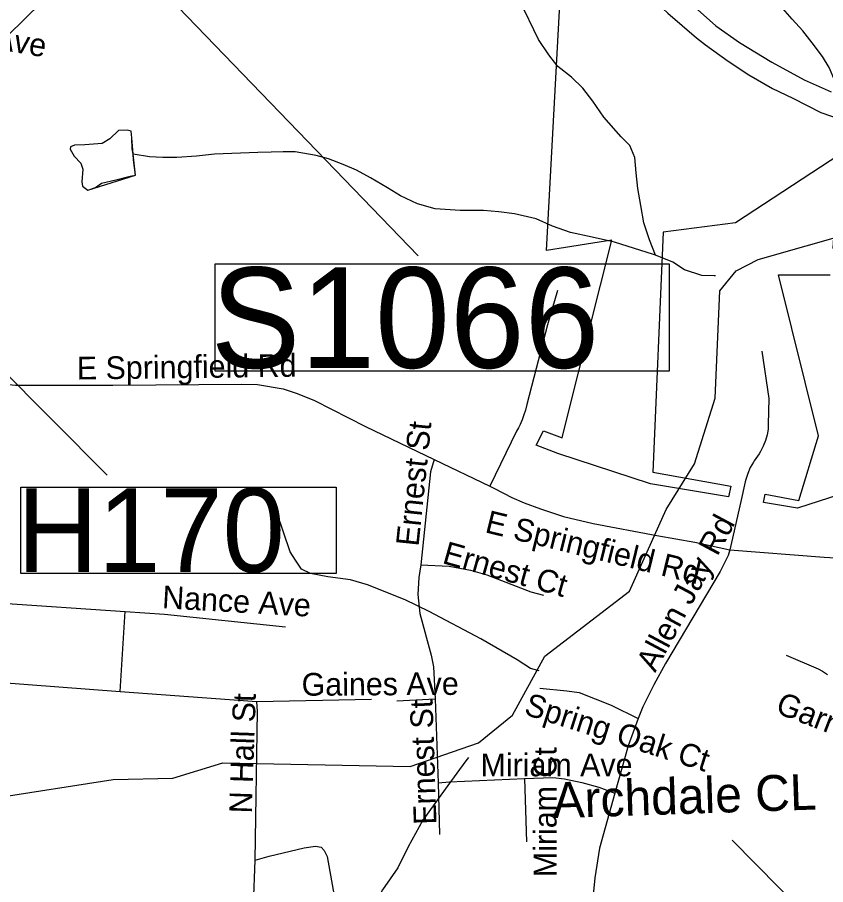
# Model space of a CAD drawing. Extents: x 1662474 to 1856135, y 779280 to 917889.
# Drawn here: x 1713266 to 1716644, y 793848 to 797474 of the extents above; entities that cross this region are included whole.
import ezdxf

# ---------------------------------------------------------------- set-up
doc = ezdxf.new("R2010")
doc.units = 0
for name, color, linetype in [('Exist Boundary Political City Limit New', 7, 'Continuous'), ('Exist Civil Demographics Community Label', 7, 'Continuous'), ('Exist Hydrographic Misc Water Feature', 7, 'Continuous'), ('Exist Road Non-System Structure Non-Sys NCDOT Number Label', 7, 'Continuous'), ('Exist Road Non-System Type 51', 7, 'Continuous'), ('Exist Road Non-System Type 51 Label', 7, 'Continuous'), ('Exist Road Primary Interstate Structure Ovrhead Sign CELL', 7, 'Continuous'), ('Exist Road Secondary Type 51 Attributed', 7, 'Continuous'), ('Map Preparation Boundary City Limit Buffer Line', 7, 'Continuous'), ('Prop Road Primary US Projected', 7, 'Continuous')]:
    doc.layers.add(name, color=color, linetype=linetype)

msp = doc.modelspace()

# ---------------------------------------------------------------- linework, layer by layer
at = {"layer": 'Exist Boundary Political City Limit New'}
for points in [[(1716702.8, 796899.9), (1716268.1, 796614.9), (1715965, 796575.8), (1715921.4, 795572.2), (1716247.5, 795514), (1716238.8, 795469.1), (1715912.2, 795523.2), (1715524.6, 795651.2), (1715433.9, 795685.2), (1715465, 795745.6), (1715542.5, 795716.4), (1715562.2, 795795), (1715750, 796541.9), (1715477.8, 796498.7), (1715559, 797993.3)], [(1716703.4, 795479.2), (1716526.9, 795422.6), (1716384.9, 795445.5), (1716391.5, 795480.4), (1716532.8, 795454.2), (1716614.9, 795724), (1716447.4, 796397.8)], [(1716447.4, 796397.8), (1716663.1, 796398.1)]]:
    msp.add_lwpolyline(points, dxfattribs=at)
at = {"layer": 'Exist Civil Demographics Community Label'}
msp.add_lwpolyline([(1717340.7, 792090.9), (1717237.1, 793036.3), (1716252.9, 794033.4)], dxfattribs=at)
at = {"layer": 'Exist Hydrographic Misc Water Feature'}
for points in [[(1715933.2, 796479), (1715907.8, 796543.3), (1715884.4, 796615.5), (1715871.2, 796687.6), (1715859.8, 796757.8), (1715852.5, 796823.8), (1715847.1, 796887.9), (1715825.5, 796938.2), (1715789.8, 796974.4), (1715716.6, 797057.2), (1715671.2, 797123.6), (1715629.7, 797178.1), (1715582.2, 797224.5), (1715524.6, 797269.1), (1715487, 797317.4), (1715443.6, 797381.9), (1715365, 797546.6), (1715335.7, 797609), (1715245.2, 797767.8), (1715223.5, 797796.1), (1715187.7, 797820.5), (1715149.8, 797836.8), (1714951.9, 797846.7), (1714915.8, 797839)], [(1716675.7, 796508), (1716680.6, 796599.9), (1716687.6, 796709.9), (1716698.5, 796801.8), (1716709.9, 796949.7), (1716710.5, 797005.8), (1716709.3, 797087.8), (1716703.6, 797133.9), (1716682.3, 797208.2), (1716658.8, 797264.3), (1716631.3, 797310.6), (1716587.9, 797367), (1716548.2, 797417.5), (1716504.7, 797465.9), (1716465.1, 797510.3), (1716427.6, 797562.6), (1716392.3, 797623), (1716364.6, 797663.3), (1716287.6, 797772), (1716263.9, 797800.2), (1716250, 797816.3)], [(1713750.6, 796901.8), (1713746.8, 796923.7), (1713745.1, 796969.8), (1713741.4, 796997.9), (1713725.6, 797002), (1713689.5, 797000.3), (1713653.2, 796966.7), (1713620.9, 796947), (1713548.9, 796941.6), (1713504.8, 796940.1), (1713488.8, 796932.3), (1713486.7, 796922.3), (1713504.4, 796894.1), (1713532.2, 796863.8), (1713539.9, 796839.7), (1713535.4, 796785.7), (1713539.2, 796767.7), (1713561, 796751.5), (1713593.2, 796763.2), (1713617.4, 796780.9), (1713677.6, 796794.4), (1713737.7, 796809.8), (1713759.8, 796813.6), (1713752.3, 796877.7), (1713750.6, 796901.8)], [(1713750.6, 796901.8), (1713745.1, 796969.8), (1713741.4, 796997.9), (1713725.6, 797002), (1713689.5, 797000.3), (1713653.2, 796966.7), (1713620.9, 796947), (1713548.9, 796941.6), (1713504.8, 796940.1), (1713488.8, 796932.3), (1713486.7, 796922.3), (1713504.4, 796894.1), (1713532.2, 796863.8), (1713539.9, 796839.7), (1713535.4, 796785.7), (1713539.2, 796767.7), (1713561, 796751.5), (1713759.8, 796813.6), (1713750.6, 796901.8)], [(1714326.8, 796910.3), (1714270.8, 796908.8), (1714090.6, 796902.5), (1714014.6, 796893.2), (1713932.6, 796888), (1713874.4, 796888.6), (1713818.5, 796891.1), (1713750.6, 796901.8)], [(1715933.2, 796479), (1715925.3, 796483), (1715761.7, 796534.6), (1715667.8, 796555.5), (1715578.1, 796574.4), (1715502.2, 796601), (1715434.5, 796631.8), (1715344.6, 796652.6), (1715278.7, 796661.3), (1715214.8, 796665.8), (1715116.8, 796666.8), (1715012.8, 796673.7), (1714939, 796694.4), (1714867.2, 796727.2), (1714813.6, 796761.7), (1714741.9, 796802.3), (1714684.2, 796834.9), (1714628.4, 796859.4), (1714566.6, 796882), (1714514.8, 796896.5), (1714426.8, 796911.3), (1714376.8, 796911.8), (1714326.8, 796910.3)], [(1711608.1, 795265.3), (1711922.1, 795019.3), (1712566.1, 794339.9), (1712740.2, 794254.3), (1712915.2, 794211.4), (1713165.1, 794209.6), (1713666.2, 794288.1), (1713916.2, 794292.8), (1714125.2, 794357.5), (1714908.2, 794341.6), (1715193.2, 794440.8), (1715335.2, 794556.1), (1715471.2, 794802.8), (1715824.2, 795074.6), (1715977.2, 795416.2), (1716096.2, 795607.4), (1716182.2, 795881.4), (1716202.2, 796330.6), (1716270.3, 796414.6), (1716362.2, 796461.9), (1716763.2, 796575.3)], [(1716184.4, 796392.6), (1716178.5, 796392.6), (1716126.5, 796395.1), (1716054.7, 796417.8), (1716004.9, 796450.2), (1715933.2, 796479)], [(1715446.9, 794741.5), (1715410.7, 794751.4), (1715355.1, 794787.9), (1715203.8, 794875.4), (1714986.8, 794989.4), (1714887.3, 795038.4), (1714729.8, 795102), (1714658, 795122.6), (1714564, 795135.5), (1714492.1, 795148.2), (1714454.4, 795166.6), (1714428.7, 795204.8), (1714407, 795239), (1714350.6, 795403.6), (1714342.8, 795429.7)], [(1715151.2, 794379.7), (1715141, 794365.8), (1715053.8, 794246.6), (1714960.6, 794117.5), (1714899.6, 794006), (1714856.7, 793918.3), (1714791.8, 793826.9), (1714746.9, 793737.3), (1714661.5, 793598.1), (1714625, 793542.4), (1714590.6, 793492.7), (1714550.2, 793443.1), (1714507.5, 793385.5), (1714424.3, 793258.2), (1714375.4, 793168.7), (1714310.3, 793051.3), (1714229.2, 792925.9), (1714180.6, 792870.4), (1714136.1, 792820.9), (1714089.6, 792779.3), (1714033.2, 792737.8), (1713986.9, 792700.2)]]:
    msp.add_lwpolyline(points, dxfattribs=at)
at = {"layer": 'Exist Road Non-System Structure Non-Sys NCDOT Number Label'}
msp.add_line((1710361.9, 798852.7), (1713642, 795560.3), dxfattribs=at)
msp.add_lwpolyline([(1713281.6, 795510), (1714598.7, 795510), (1714598.7, 795148.9), (1713281.6, 795148.9)], close=True, dxfattribs=at)
at = {"layer": 'Exist Road Non-System Type 51'}
for p, q in [((1715008.1, 795626), (1715240.9, 795513.4)), ((1712992.1, 795039.9), (1713717.6, 794989.9)), ((1713696.2, 794656.2), (1713717.6, 794989.9)), ((1712972.1, 794709.5), (1713696.2, 794656.2)), ((1713696.2, 794656.2), (1714266.6, 794614.2)), ((1714266.6, 794614.2), (1714746.4, 794623.7)), ((1714851.9, 794616.4), (1715012, 794625)), ((1715012, 794625), (1715024.9, 794273.9)), ((1715386.2, 794291.2), (1715394.4, 794027.1)), ((1715024.9, 794273.9), (1715029.9, 794057.2)), ((1714247.1, 793634.4), (1714260.6, 793950.8))]:
    msp.add_line(p, q, dxfattribs=at)
for points in [[(1715523.6, 796332.6), (1715481.9, 796189), (1715394.9, 795854.9), (1715389.6, 795832.1), (1715383.6, 795812.1), (1715376.6, 795791.7), (1715367.9, 795772.2), (1715360.6, 795758), (1715352.4, 795743.9), (1715240.9, 795513.4)], [(1712701, 796145.4), (1712740.4, 796124.2), (1712791.9, 796106.9), (1713095.2, 795965.9), (1713142.5, 795951.8), (1713188.9, 795942.9), (1713258, 795936.5), (1713665.1, 795935.8), (1714205.1, 795940.2), (1714269.8, 795938.6), (1714377.1, 795921), (1714436.1, 795901.6), (1714508.1, 795871.4), (1714720.9, 795763.6), (1715008.1, 795626)], [(1716378, 796077.8), (1716407.2, 795880.9), (1716404.6, 795772), (1716403.4, 795752.6), (1716399.4, 795728.2), (1716392.8, 795704.2), (1716383.6, 795681.2), (1716372, 795659.4), (1716365.8, 795649.6), (1716345.8, 795619.9), (1716342, 795614.2), (1716329.1, 795591.4), (1716318.6, 795567.2), (1716310.6, 795542.2), (1716308.1, 795532.2), (1716290, 795449.6), (1716243.2, 795248.1)], [(1715008.1, 795626), (1714992.4, 795573.2), (1714951.9, 795185.6)], [(1715240.9, 795513.4), (1715260.6, 795503.7), (1715332.2, 795467), (1715383.9, 795444.4), (1715452.4, 795418.7), (1715548.2, 795386.7), (1715672.6, 795357.8), (1715939, 795307.9), (1716098.1, 795279.9), (1716243.2, 795248.1)], [(1716243.2, 795248.1), (1716236.6, 795223.4), (1716203.1, 795156.8), (1715975, 794772), (1715926.6, 794683.2), (1715880.2, 794591.4), (1715861.1, 794542.1)], [(1716243.2, 795248.1), (1716637.4, 795217.1), (1716780, 795208.2), (1716965.8, 795205.9), (1716987.9, 795211.1)], [(1714951.9, 795185.6), (1714944, 795132.4), (1714939.4, 795061.2), (1714948.5, 794981.4), (1714995.8, 794807.7), (1715004.9, 794758.1), (1715012, 794625)], [(1714951.9, 795185.6), (1715071.4, 795179.4), (1715160.1, 795163), (1715228.2, 795143.1), (1715411.5, 795071.7), (1715464.5, 795058.4)], [(1713717.6, 794989.9), (1713881.9, 794978.5), (1714386.6, 794926)], [(1716478.6, 794807.9), (1716613, 794749.9), (1716630.9, 794740.8), (1716639.2, 794735.5), (1716651.9, 794726.9)], [(1715449.5, 794669.1), (1715562.6, 794658.9), (1715614.1, 794650.7), (1715747.9, 794597.9), (1715861.1, 794542.1)], [(1714260.6, 793950.8), (1714270, 794572), (1714266.6, 794614.2)], [(1715861.1, 794542.1), (1715818.4, 794427.9), (1715763.1, 794231)], [(1715024.9, 794273.9), (1715071.9, 794278.5), (1715386.2, 794291.2)], [(1715386.2, 794291.2), (1715503.9, 794295.9), (1715553.2, 794290.9), (1715625.9, 794274.9), (1715695.8, 794255.2), (1715763.1, 794231)], [(1715763.1, 794231), (1715699.6, 793999.9), (1715680.2, 793877.2), (1715673.9, 793819), (1715669.2, 793502.4)], [(1714260.6, 793950.8), (1714318.6, 793967.2), (1714465.1, 794001.4), (1714512.9, 794008.8), (1714535.4, 794005.1), (1714548.8, 793990.9), (1714560.4, 793965.9), (1714592.6, 793786.2), (1714600.8, 793769.1), (1714611.5, 793755.2), (1714640.4, 793735.8), (1714662.9, 793730.2), (1715316.1, 793685.9), (1715344.2, 793686.2), (1715366.6, 793675.4), (1715375.8, 793666.8), (1715385.5, 793650.5), (1715390.2, 793619), (1715388.6, 793546.5), (1715393.4, 793535.5), (1715408.9, 793524.5), (1715669.2, 793502.4)]]:
    msp.add_lwpolyline(points, dxfattribs=at)
at = {"layer": 'Exist Road Primary Interstate Structure Ovrhead Sign CELL'}
msp.add_line((1711874.2, 799656.4), (1714941.8, 796476.9), dxfattribs=at)
msp.add_lwpolyline([(1714093.7, 796443.4), (1715989.7, 796443.4), (1715989.7, 795994.5), (1714093.7, 795994.5)], close=True, dxfattribs=at)
at = {"layer": 'Exist Road Secondary Type 51 Attributed'}
msp.add_lwpolyline([(1711980.1, 792720.4), (1712057.3, 793192.1), (1712117.7, 793573.1), (1712168.9, 793949.6), (1712234, 794372.5), (1712271.2, 794651.3), (1712289.2, 794759), (1712329.2, 794912.6), (1712473.9, 795357.1), (1712559.9, 795520.4), (1712593.7, 795605.5), (1712625.8, 795705.1), (1712648.3, 795803), (1712674.7, 795925.5), (1712699.3, 796156.8), (1712781.9, 796663.3), (1712836.2, 796867.3), (1712887.2, 796972.5), (1712944.6, 797071.4), (1713225.3, 797396.5), (1713368.9, 797536.8), (1713589, 797689.8), (1713974.4, 797851.7), (1714335.6, 798017.4)], dxfattribs=at)
at = {"layer": 'Map Preparation Boundary City Limit Buffer Line'}
for points in [[(1716702.8, 796899.9), (1716268.1, 796614.9), (1715965, 796575.8), (1715921.4, 795572.2), (1716247.5, 795514), (1716238.8, 795469.1), (1715912.2, 795523.2), (1715524.6, 795651.2), (1715433.9, 795685.2), (1715465, 795745.6), (1715542.5, 795716.4), (1715562.2, 795795), (1715750, 796541.9), (1715477.8, 796498.7), (1715559, 797993.3)], [(1716703.4, 795479.2), (1716526.9, 795422.6), (1716384.9, 795445.5), (1716391.5, 795480.4), (1716532.8, 795454.2), (1716614.9, 795724), (1716447.4, 796397.8)], [(1716447.4, 796397.8), (1716663.1, 796398.1)]]:
    msp.add_lwpolyline(points, dxfattribs=at)
at = {"layer": 'Prop Road Primary US Projected'}
for points in [[(1714306.7, 798826.7), (1714610.5, 798651.1), (1714923.8, 798466), (1715137.4, 798356.8), (1715303.5, 798242.9), (1715461.6, 798127.8), (1715607, 798002.5), (1715822.4, 797787), (1715920.2, 797684.3), (1716045.5, 797564), (1716185.8, 797438.7), (1716283.5, 797368.6), (1716418.8, 797285.9), (1716554.1, 797213.2), (1716666.9, 797163.1)], [(1714902.9, 798377.4), (1715012.5, 798310.9), (1715185.2, 798206.6), (1715300.2, 798127.5), (1715381.2, 798068.2), (1715496.2, 797971.1), (1715600.5, 797875.8), (1715708.4, 797766.1), (1715812.9, 797658.2), (1715921.4, 797551.2), (1715984.1, 797491.6), (1716045.2, 797439.6), (1716104.8, 797387.7), (1716141.5, 797358.6), (1716236.3, 797291.4), (1716323.4, 797233.3), (1716422.7, 797176.8), (1716506.8, 797135.5), (1716624.4, 797075.9), (1716713.1, 797045.3)]]:
    msp.add_lwpolyline(points, dxfattribs=at)

# ---------------------------------------------------------------- texts
at = {"layer": 'Exist Civil Demographics Community Label'}
msp.add_text('Archdale CL', height=150, rotation=1.9039, dxfattribs=at).set_placement((1715505, 794125.6))
at = {"layer": 'Exist Road Non-System Structure Non-Sys NCDOT Number Label'}
msp.add_text('H170', height=350, dxfattribs=at).set_placement((1713265.5, 795155))
at = {"layer": 'Exist Road Non-System Type 51 Label'}
for s, rotation, p in [('Townsend Ave', 350.3058, (1712551.1, 797448.1)), ('E Springfield Rd', 0.7428, (1713515.5, 795959.7)), ('Ernest St', 84.0365, (1714942.7, 795259.7)), ('E Springfield Rd', 346.2336, (1715216.6, 795321.8)), ('Allen Jay Rd', 61.8597, (1715932, 794731.9)), ('Ernest Ct', 344.3092, (1715038.1, 795193)), ('Nance Ave', 356.7034, (1713869.7, 795003.9)), ('Gaines Ave', 0.3266, (1714454.5, 794637.7)), ('N Hall St', 88.0695, (1714246.2, 794144.7)), ('Ernest St', 91.8562, (1715018.2, 794100.1)), ('Spring Oak Ct', 342.3844, (1715379.5, 794561.1)), ('Garnett Dr', 339.0212, (1716430.2, 794567.8)), ('Miriam Ct', 90, (1715519.6, 793879.4))]:
    msp.add_text(s, height=95, rotation=rotation, dxfattribs=at).set_placement(p)
msp.add_text('Miriam Ave', height=95, dxfattribs=at).set_placement((1715201.9, 794301.2))
at = {"layer": 'Exist Road Primary Interstate Structure Ovrhead Sign CELL'}
msp.add_text('S1066', height=420, dxfattribs=at).set_placement((1714074.4, 796008.4))

doc.saveas('drawing.dxf')
